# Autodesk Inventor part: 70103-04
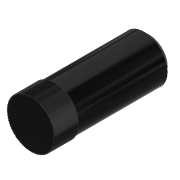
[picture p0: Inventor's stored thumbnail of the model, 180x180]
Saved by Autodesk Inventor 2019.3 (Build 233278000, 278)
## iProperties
Created: 2012-10
Part Number: 70103-04
Material: Ogólny
Document SubType Name: Modeling
Designer: CADENGINEERING4
Density: 1 g/cm^3
Appearance: Gładki — czarny
Author: CADENGINEERING4
Revision Number: ÈÎºÎ
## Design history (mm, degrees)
feature "ÕóÁÐ(Ô²ÖÜ)1"
node "Bryła1"
